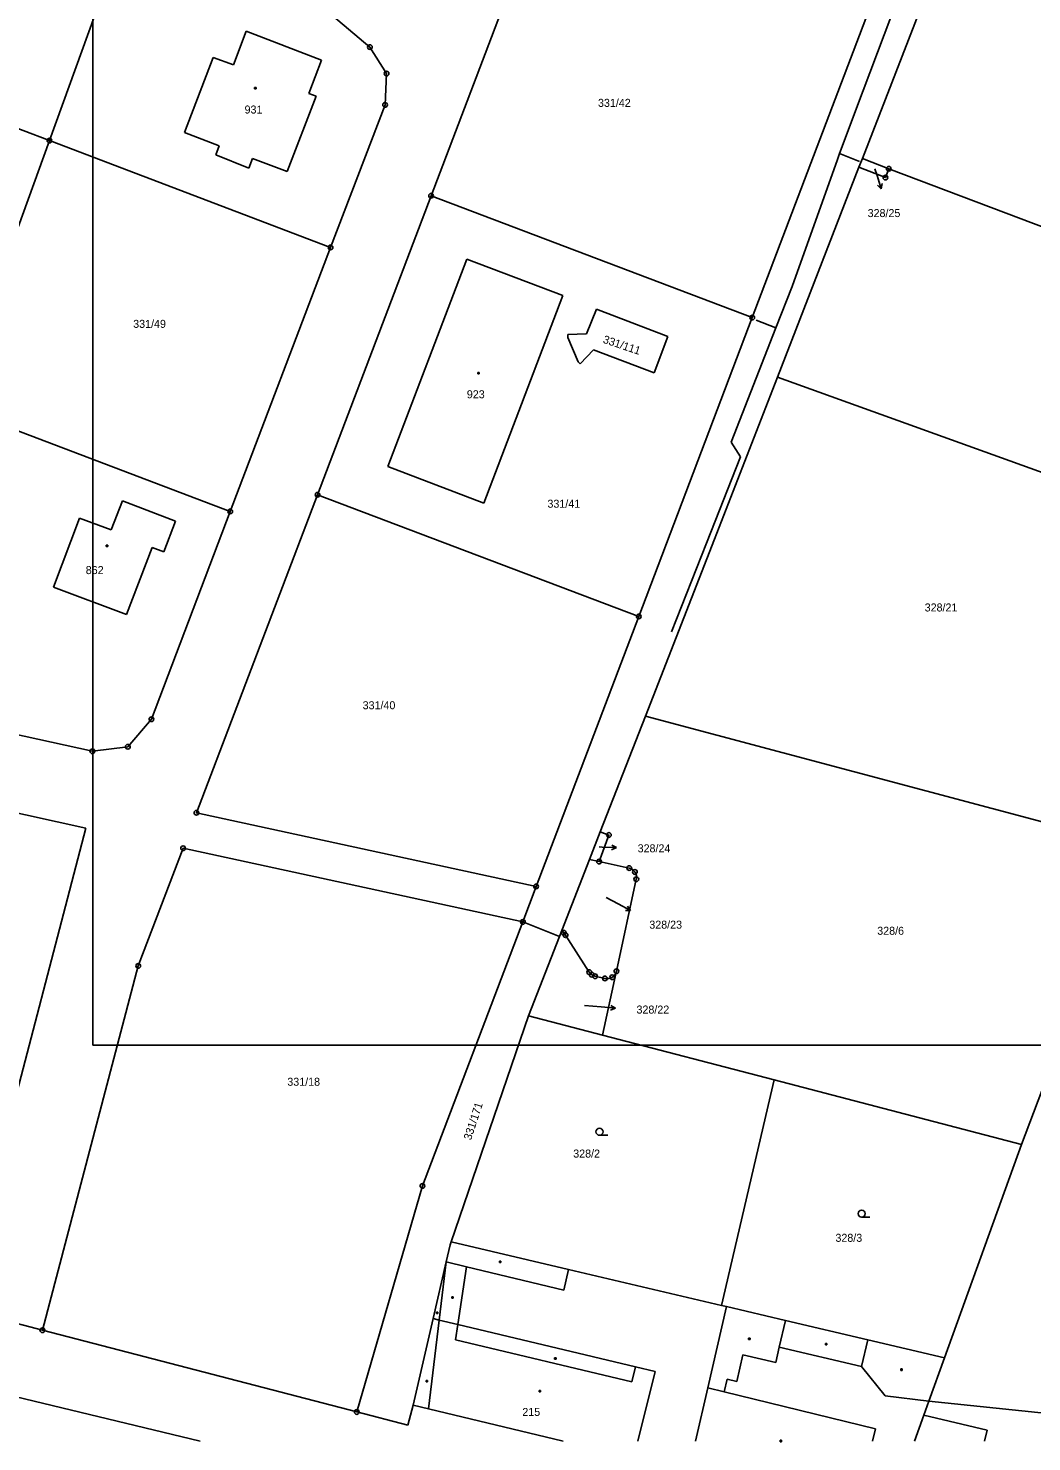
# Model space of a CAD drawing. Extents: x -770973 to -770265, y -1049936 to -1049427.
# Drawn here: x -770865.5 to -770758.9, y -1049934.8 to -1049784.7 of the extents above; entities that cross this region are included whole.
import ezdxf

# ---------------------------------------------------------------- set-up
doc = ezdxf.new("R2010")
doc.units = 0
for name, color, linetype in [('Vrstva 1', 7, 'Continuous'), ('Vrstva 13', 7, 'Continuous'), ('Vrstva 14', 7, 'Continuous'), ('Vrstva 15', 7, 'Continuous'), ('Vrstva 16', 7, 'Continuous'), ('Vrstva 2', 7, 'Continuous'), ('Vrstva 23', 7, 'Continuous'), ('Vrstva 25', 7, 'Continuous'), ('Vrstva 28', 7, 'Continuous'), ('Vrstva 50', 7, 'Continuous'), ('Vrstva 63', 7, 'Continuous')]:
    doc.layers.add(name, color=color, linetype=linetype)

msp = doc.modelspace()

# ---------------------------------------------------------------- linework, layer by layer
at = {"layer": 'Vrstva 1'}
for p, q in [((-770776.92, -1049798.48), (-770755.85, -1049744.21)), ((-770863.27, -1049796.58), (-770852.53, -1049767)), ((-770829.23, -1049786.65), (-770852.53, -1049767)), ((-770822.73, -1049802.44), (-770810.63, -1049770.66)), ((-770788.61, -1049815.38), (-770776.56, -1049783.61)), ((-770893.23, -1049785.23), (-770863.27, -1049796.58)), ((-770842.38, -1049784.96), (-770843.73, -1049788.53)), ((-770834.36, -1049788.05), (-770842.38, -1049784.96)), ((-770827.45, -1049789.46), (-770829.23, -1049786.65)), ((-770845.86, -1049787.74), (-770848.93, -1049795.72)), ((-770843.73, -1049788.53), (-770845.86, -1049787.74)), ((-770835.73, -1049791.59), (-770834.36, -1049788.05)), ((-770827.62, -1049792.79), (-770827.45, -1049789.46)), ((-770838, -1049799.87), (-770834.95, -1049791.88)), ((-770834.95, -1049791.88), (-770835.73, -1049791.59)), ((-770833.4, -1049807.94), (-770827.62, -1049792.79)), ((-770873.5, -1049824.8), (-770863.27, -1049796.58)), ((-770863.27, -1049796.58), (-770833.4, -1049807.94)), ((-770848.93, -1049795.72), (-770845.24, -1049797.13)), ((-770845.24, -1049797.13), (-770845.61, -1049798.11)), ((-770845.61, -1049798.11), (-770842.08, -1049799.5)), ((-770842.08, -1049799.5), (-770841.69, -1049798.48)), ((-770841.69, -1049798.48), (-770838, -1049799.87)), ((-770785.94, -1049821.72), (-770777.28, -1049799.41)), ((-770777.28, -1049799.41), (-770776.92, -1049798.48)), ((-770774.47, -1049800.51), (-770777.28, -1049799.41)), ((-770776.92, -1049798.48), (-770774.11, -1049799.58)), ((-770774.11, -1049799.58), (-770774.47, -1049800.51)), ((-770723.9, -1049818.61), (-770774.11, -1049799.58)), ((-770822.73, -1049802.44), (-770834.79, -1049834.21)), ((-770822.73, -1049802.44), (-770788.61, -1049815.38)), ((-770833.4, -1049807.94), (-770844.07, -1049835.99)), ((-770818.92, -1049809.17), (-770827.31, -1049831.2)), ((-770808.73, -1049813.05), (-770818.92, -1049809.17)), ((-770817.12, -1049835.1), (-770808.73, -1049813.05)), ((-770806.22, -1049817.11), (-770805.17, -1049814.48)), ((-770805.17, -1049814.48), (-770797.57, -1049817.39)), ((-770800.67, -1049847.14), (-770788.61, -1049815.38)), ((-770808.2, -1049817.17), (-770806.22, -1049817.11)), ((-770808.2, -1049817.5), (-770808.2, -1049817.17)), ((-770807.11, -1049820.08), (-770808.2, -1049817.5)), ((-770797.57, -1049817.39), (-770799.05, -1049821.25)), ((-770805.47, -1049818.82), (-770806.88, -1049820.29)), ((-770799.05, -1049821.25), (-770805.47, -1049818.82)), ((-770806.88, -1049820.29), (-770807.11, -1049820.08)), ((-770792.62, -1049838.92), (-770785.94, -1049821.72)), ((-770735.94, -1049839.73), (-770785.94, -1049821.72)), ((-770844.07, -1049835.99), (-770873.5, -1049824.8)), ((-770827.31, -1049831.2), (-770817.12, -1049835.1)), ((-770834.79, -1049834.21), (-770847.66, -1049867.99)), ((-770834.79, -1049834.21), (-770800.67, -1049847.14)), ((-770856.7, -1049837.95), (-770855.51, -1049834.85)), ((-770855.51, -1049834.85), (-770849.86, -1049837)), ((-770862.85, -1049844.02), (-770860.07, -1049836.69)), ((-770860.07, -1049836.69), (-770856.7, -1049837.95)), ((-770844.07, -1049835.99), (-770852.43, -1049858.06)), ((-770849.86, -1049837), (-770851.1, -1049840.27)), ((-770852.35, -1049839.8), (-770855.07, -1049846.94)), ((-770851.1, -1049840.27), (-770852.35, -1049839.8)), ((-770792.62, -1049838.92), (-770799.97, -1049857.75)), ((-770855.07, -1049846.94), (-770862.85, -1049844.02)), ((-770811.57, -1049875.82), (-770800.67, -1049847.14)), ((-770884.71, -1049855.76), (-770858.71, -1049861.47)), ((-770854.94, -1049860.98), (-770852.43, -1049858.06)), ((-770804.76, -1049870.02), (-770799.97, -1049857.75)), ((-770747.99, -1049871.56), (-770799.97, -1049857.75)), ((-770899.58, -1049860.79), (-770859.41, -1049869.62)), ((-770858.71, -1049861.47), (-770854.94, -1049860.98)), ((-770847.66, -1049867.99), (-770811.57, -1049875.82)), ((-770872.73, -1049920.7), (-770859.41, -1049869.62)), ((-770805.9, -1049872.96), (-770804.76, -1049870.02)), ((-770804.76, -1049870.02), (-770803.84, -1049870.36)), ((-770849.07, -1049871.77), (-770853.84, -1049884.27)), ((-770812.98, -1049879.6), (-770849.07, -1049871.77)), ((-770803.84, -1049870.36), (-770804.89, -1049873.18)), ((-770805.9, -1049872.96), (-770808.84, -1049880.5)), ((-770804.89, -1049873.18), (-770805.9, -1049872.96)), ((-770804.89, -1049873.18), (-770801.68, -1049873.87)), ((-770812.98, -1049879.6), (-770811.57, -1049875.82)), ((-770803.05, -1049884.83), (-770800.93, -1049875.06)), ((-770823.65, -1049907.64), (-770812.98, -1049879.6)), ((-770812.98, -1049879.6), (-770809.09, -1049881.13)), ((-770808.84, -1049880.5), (-770809.09, -1049881.13)), ((-770808.84, -1049880.5), (-770808.64, -1049880.74)), ((-770808.64, -1049880.74), (-770808.45, -1049881)), ((-770809.09, -1049881.13), (-770812.38, -1049889.56)), ((-770808.45, -1049881), (-770805.93, -1049884.93)), ((-770853.84, -1049884.27), (-770864.02, -1049922.97)), ((-770805.93, -1049884.93), (-770805.67, -1049885.2)), ((-770805.67, -1049885.2), (-770805.31, -1049885.37)), ((-770804.52, -1049891.61), (-770803.08, -1049884.93)), ((-770803.08, -1049884.93), (-770803.05, -1049884.83)), ((-770805.31, -1049885.37), (-770804.26, -1049885.59)), ((-770820.6, -1049913.58), (-770812.38, -1049889.56)), ((-770804.52, -1049891.61), (-770812.38, -1049889.56)), ((-770786.3, -1049896.37), (-770804.52, -1049891.61)), ((-770791.87, -1049920.34), (-770786.3, -1049896.37)), ((-770760.01, -1049903.23), (-770786.3, -1049896.37)), ((-770760.01, -1049903.23), (-770757.85, -1049897.54)), ((-770760.01, -1049903.23), (-770768.19, -1049925.91)), ((-770830.63, -1049931.66), (-770823.65, -1049907.64)), ((-770820.71, -1049913.9), (-770820.6, -1049913.58)), ((-770808.12, -1049916.52), (-770820.6, -1049913.58)), ((-770820.71, -1049913.9), (-770821.13, -1049915.72)), ((-770821.13, -1049915.72), (-770822.52, -1049921.74)), ((-770791.87, -1049920.34), (-770808.12, -1049916.52)), ((-770872.73, -1049920.7), (-770864.02, -1049922.97)), ((-770793.35, -1049929.1), (-770791.35, -1049920.46)), ((-770791.35, -1049920.46), (-770791.87, -1049920.34)), ((-770785.07, -1049921.94), (-770791.35, -1049920.46)), ((-770822.52, -1049921.74), (-770824.65, -1049930.95)), ((-770776.35, -1049923.99), (-770785.07, -1049921.94)), ((-770864.02, -1049922.97), (-770830.63, -1049931.66)), ((-770768.19, -1049925.91), (-770776.35, -1049923.99)), ((-770847.27, -1049934.76), (-770879.31, -1049927.05)), ((-770768.19, -1049925.91), (-770769.85, -1049930.5)), ((-770794.66, -1049934.76), (-770793.35, -1049929.1)), ((-770830.63, -1049931.66), (-770825.19, -1049933.06)), ((-770825.19, -1049933.06), (-770824.65, -1049930.95)), ((-770824.65, -1049930.95), (-770823.02, -1049931.34)), ((-770823.02, -1049931.34), (-770808.7, -1049934.76)), ((-770769.85, -1049930.5), (-770770.4, -1049932.01)), ((-770740.24, -1049933.6), (-770769.85, -1049930.5)), ((-770770.4, -1049932.01), (-770771.39, -1049934.76)), ((-770763.67, -1049933.58), (-770770.4, -1049932.01)), ((-770763.67, -1049933.58), (-770763.94, -1049934.75))]:
    msp.add_line(p, q, dxfattribs=at)
for centre, radius, start, end in [((-770801.92, -1049874.85), 1.01, 348.2367, 76.2058), ((-770804.01, -1049884.65), 0.974, 255.2851, 343.1534)]:
    msp.add_arc(centre, radius, start, end, dxfattribs=at)
at = {"layer": 'Vrstva 13'}
for p, q in [((-770775.58, -1049799.6), (-770775.36, -1049800.28)), ((-770804.89, -1049871.63), (-770804.54, -1049871.64)), ((-770804.14, -1049876.99), (-770802.85, -1049877.68)), ((-770806.44, -1049888.49), (-770804.65, -1049888.63))]:
    msp.add_line(p, q, dxfattribs=at)
at = {"layer": 'Vrstva 16'}
for p, q in [((-770775.36, -1049800.28), (-770774.91, -1049801.71)), ((-770774.91, -1049801.71), (-770774.82, -1049801.16)), ((-770774.91, -1049801.71), (-770775.3, -1049801.31)), ((-770804.54, -1049871.64), (-770803.04, -1049871.69)), ((-770803.04, -1049871.69), (-770803.55, -1049871.93)), ((-770803.04, -1049871.69), (-770803.53, -1049871.43)), ((-770802.85, -1049877.68), (-770801.53, -1049878.39)), ((-770801.53, -1049878.39), (-770802.09, -1049878.37)), ((-770801.53, -1049878.39), (-770801.85, -1049877.93)), ((-770804.65, -1049888.63), (-770803.15, -1049888.74)), ((-770803.15, -1049888.74), (-770803.67, -1049888.96)), ((-770803.15, -1049888.74), (-770803.63, -1049888.46))]:
    msp.add_line(p, q, dxfattribs=at)
at = {"layer": 'Vrstva 2'}
for p, q in [((-770821.13, -1049915.72), (-770821.88, -1049921.89)), ((-770818.95, -1049916.24), (-770821.13, -1049915.72)), ((-770818.95, -1049916.24), (-770819.88, -1049922.36)), ((-770818.95, -1049916.24), (-770808.64, -1049918.7)), ((-770808.64, -1049918.7), (-770808.12, -1049916.52)), ((-770821.88, -1049921.89), (-770823.02, -1049931.34)), ((-770822.52, -1049921.74), (-770821.88, -1049921.89)), ((-770819.88, -1049922.36), (-770821.88, -1049921.89)), ((-770819.88, -1049922.36), (-770820.12, -1049923.98)), ((-770819.88, -1049922.36), (-770801.02, -1049926.85)), ((-770785.07, -1049921.94), (-770785.74, -1049924.77)), ((-770820.12, -1049923.98), (-770801.4, -1049928.44)), ((-770776.35, -1049923.99), (-770777.02, -1049926.83)), ((-770789.6, -1049925.58), (-770790.27, -1049928.41)), ((-770789.6, -1049925.58), (-770786.12, -1049926.4)), ((-770785.74, -1049924.77), (-770786.12, -1049926.4)), ((-770785.74, -1049924.77), (-770777.02, -1049926.83)), ((-770801.4, -1049928.44), (-770801.02, -1049926.85)), ((-770801.02, -1049926.85), (-770798.92, -1049927.35)), ((-770798.92, -1049927.35), (-770800.78, -1049934.76)), ((-770774.48, -1049929.96), (-770777.02, -1049926.83)), ((-770791.28, -1049928.17), (-770791.61, -1049929.52)), ((-770791.28, -1049928.17), (-770790.27, -1049928.41)), ((-770793.35, -1049929.1), (-770791.61, -1049929.52)), ((-770791.61, -1049929.52), (-770775.51, -1049933.45)), ((-770769.85, -1049930.5), (-770774.48, -1049929.96)), ((-770775.83, -1049934.76), (-770775.51, -1049933.45))]:
    msp.add_line(p, q, dxfattribs=at)
at = {"layer": 'Vrstva 23'}
for p, q in [((-770804.84, -1049902.26), (-770803.96, -1049902.26)), ((-770776.99, -1049910.97), (-770776.11, -1049910.97))]:
    msp.add_line(p, q, dxfattribs=at)
for centre in [(-770804.84, -1049901.89), (-770776.99, -1049910.59)]:
    msp.add_circle(centre, 0.375, dxfattribs=at)
at = {"layer": 'Vrstva 25'}
for p, q in [((-770841.47, -1049790.94), (-770841.32, -1049790.94)), ((-770841.47, -1049791.09), (-770841.47, -1049790.94)), ((-770841.32, -1049791.09), (-770841.47, -1049791.09)), ((-770841.32, -1049790.94), (-770841.32, -1049791.09)), ((-770817.78, -1049821.23), (-770817.63, -1049821.23)), ((-770817.78, -1049821.38), (-770817.78, -1049821.23)), ((-770817.63, -1049821.38), (-770817.78, -1049821.38)), ((-770817.63, -1049821.23), (-770817.63, -1049821.38)), ((-770857.23, -1049839.57), (-770857.08, -1049839.57)), ((-770857.23, -1049839.72), (-770857.23, -1049839.57)), ((-770857.08, -1049839.72), (-770857.23, -1049839.72)), ((-770857.08, -1049839.57), (-770857.08, -1049839.72)), ((-770815.46, -1049915.63), (-770815.31, -1049915.63)), ((-770815.46, -1049915.78), (-770815.46, -1049915.63)), ((-770815.31, -1049915.78), (-770815.46, -1049915.78)), ((-770815.31, -1049915.63), (-770815.31, -1049915.78)), ((-770820.54, -1049919.42), (-770820.39, -1049919.42)), ((-770820.54, -1049919.57), (-770820.54, -1049919.42)), ((-770820.39, -1049919.57), (-770820.54, -1049919.57)), ((-770820.39, -1049919.42), (-770820.39, -1049919.57)), ((-770822.17, -1049921.04), (-770822.02, -1049921.04)), ((-770822.17, -1049921.19), (-770822.17, -1049921.04)), ((-770822.02, -1049921.19), (-770822.17, -1049921.19)), ((-770822.02, -1049921.04), (-770822.02, -1049921.19)), ((-770789, -1049923.8), (-770788.85, -1049923.8)), ((-770789, -1049923.95), (-770789, -1049923.8)), ((-770788.85, -1049923.95), (-770789, -1049923.95)), ((-770788.85, -1049923.8), (-770788.85, -1049923.95)), ((-770780.85, -1049924.37), (-770780.7, -1049924.37)), ((-770780.85, -1049924.52), (-770780.85, -1049924.37)), ((-770780.7, -1049924.52), (-770780.85, -1049924.52)), ((-770780.7, -1049924.37), (-770780.7, -1049924.52)), ((-770809.61, -1049925.91), (-770809.46, -1049925.91)), ((-770809.61, -1049926.06), (-770809.61, -1049925.91)), ((-770809.46, -1049926.06), (-770809.61, -1049926.06)), ((-770809.46, -1049925.91), (-770809.46, -1049926.06)), ((-770772.85, -1049927.09), (-770772.7, -1049927.09)), ((-770772.85, -1049927.24), (-770772.85, -1049927.09)), ((-770772.7, -1049927.24), (-770772.85, -1049927.24)), ((-770772.7, -1049927.09), (-770772.7, -1049927.24)), ((-770823.25, -1049928.3), (-770823.1, -1049928.3)), ((-770823.25, -1049928.45), (-770823.25, -1049928.3)), ((-770823.1, -1049928.45), (-770823.25, -1049928.45)), ((-770823.1, -1049928.3), (-770823.1, -1049928.45)), ((-770811.24, -1049929.38), (-770811.09, -1049929.38)), ((-770811.24, -1049929.53), (-770811.24, -1049929.38)), ((-770811.09, -1049929.53), (-770811.24, -1049929.53)), ((-770811.09, -1049929.38), (-770811.09, -1049929.53)), ((-770785.66, -1049934.67), (-770785.51, -1049934.67)), ((-770785.66, -1049934.82), (-770785.66, -1049934.67)), ((-770785.51, -1049934.82), (-770785.66, -1049934.82)), ((-770785.51, -1049934.67), (-770785.51, -1049934.82))]:
    msp.add_line(p, q, dxfattribs=at)
at = {"layer": 'Vrstva 28'}
for centre, radius in [((-770829.23, -1049786.65), 0.25), ((-770829.23, -1049786.65), 0.005), ((-770827.45, -1049789.46), 0.25), ((-770827.45, -1049789.46), 0.005), ((-770827.62, -1049792.79), 0.25), ((-770827.62, -1049792.79), 0.005), ((-770863.27, -1049796.58), 0.25), ((-770863.27, -1049796.58), 0.005), ((-770774.11, -1049799.58), 0.25), ((-770774.11, -1049799.58), 0.005), ((-770774.47, -1049800.51), 0.25), ((-770774.47, -1049800.51), 0.005), ((-770822.73, -1049802.44), 0.25), ((-770822.73, -1049802.44), 0.005), ((-770833.4, -1049807.94), 0.25), ((-770833.4, -1049807.94), 0.005), ((-770788.61, -1049815.38), 0.25), ((-770788.61, -1049815.38), 0.005), ((-770834.79, -1049834.21), 0.25), ((-770834.79, -1049834.21), 0.005), ((-770844.07, -1049835.99), 0.25), ((-770844.07, -1049835.99), 0.005), ((-770800.67, -1049847.14), 0.25), ((-770800.67, -1049847.14), 0.005), ((-770852.43, -1049858.06), 0.25), ((-770852.43, -1049858.06), 0.005), ((-770858.71, -1049861.47), 0.25), ((-770854.94, -1049860.98), 0.25), ((-770854.94, -1049860.98), 0.005), ((-770858.71, -1049861.47), 0.005), ((-770847.66, -1049867.99), 0.25), ((-770847.66, -1049867.99), 0.005), ((-770803.84, -1049870.36), 0.25), ((-770849.07, -1049871.77), 0.25), ((-770849.07, -1049871.77), 0.005), ((-770803.84, -1049870.36), 0.005), ((-770804.89, -1049873.18), 0.25), ((-770804.89, -1049873.18), 0.005), ((-770801.68, -1049873.87), 0.25), ((-770801.68, -1049873.87), 0.005), ((-770801.08, -1049874.29), 0.25), ((-770801.08, -1049874.29), 0.005), ((-770811.57, -1049875.82), 0.25), ((-770811.57, -1049875.82), 0.005), ((-770800.93, -1049875.06), 0.25), ((-770800.93, -1049875.06), 0.005), ((-770812.98, -1049879.6), 0.25), ((-770812.98, -1049879.6), 0.005), ((-770808.64, -1049880.74), 0.25), ((-770808.45, -1049881), 0.25), ((-770808.64, -1049880.74), 0.005), ((-770808.45, -1049881), 0.005), ((-770853.84, -1049884.27), 0.25), ((-770853.84, -1049884.27), 0.005), ((-770805.93, -1049884.93), 0.25), ((-770805.93, -1049884.93), 0.005), ((-770805.67, -1049885.2), 0.25), ((-770805.67, -1049885.2), 0.005), ((-770805.31, -1049885.37), 0.25), ((-770803.49, -1049885.47), 0.25), ((-770803.05, -1049884.83), 0.25), ((-770803.05, -1049884.83), 0.005), ((-770805.31, -1049885.37), 0.005), ((-770804.26, -1049885.59), 0.25), ((-770804.26, -1049885.59), 0.005), ((-770803.49, -1049885.47), 0.005), ((-770823.65, -1049907.64), 0.25), ((-770823.65, -1049907.64), 0.005), ((-770864.02, -1049922.97), 0.25), ((-770864.02, -1049922.97), 0.005), ((-770830.63, -1049931.66), 0.25), ((-770830.63, -1049931.66), 0.005)]:
    msp.add_circle(centre, radius, dxfattribs=at)
at = {"layer": 'Vrstva 50'}
for p, q in [((-770772.14, -1049778.81), (-770776.83, -1049791.27)), ((-770776.83, -1049791.27), (-770779.34, -1049797.94)), ((-770779.34, -1049797.94), (-770779.56, -1049798.6)), ((-770779.34, -1049797.94), (-770777.23, -1049798.79)), ((-770779.56, -1049798.6), (-770784.39, -1049812.08)), ((-770784.39, -1049812.08), (-770786.1, -1049816.48)), ((-770786.1, -1049816.48), (-770788.21, -1049815.66)), ((-770786.1, -1049816.48), (-770790.84, -1049828.61)), ((-770790.84, -1049828.61), (-770789.88, -1049830.18)), ((-770789.88, -1049830.18), (-770793.49, -1049839.34)), ((-770793.49, -1049839.34), (-770797.21, -1049848.78))]:
    msp.add_line(p, q, dxfattribs=at)
at = {"layer": 'Vrstva 63'}
msp.add_lwpolyline([(-770858.67, -1049892.7), (-770264.67, -1049892.7), (-770264.67, -1049472.7), (-770858.67, -1049472.7), (-770858.67, -1049892.7)], dxfattribs=at)

# ---------------------------------------------------------------- texts
at = {"layer": 'Vrstva 14'}
for s, height, p in [('331/42', 0.85, (-770805, -1049793)), ('328/25', 0.05, (-770775.58, -1049799.6)), ('331/49', 0.85, (-770854.37, -1049816.48)), ('331/41', 0.85, (-770810.37, -1049835.59)), ('328/21', 0.85, (-770770.3, -1049846.61)), ('331/40', 0.85, (-770830, -1049857)), ('328/24', 0.05, (-770804.89, -1049871.63)), ('328/23', 0.05, (-770804.14, -1049876.99)), ('328/6', 0.85, (-770775.34, -1049880.96)), ('328/22', 0.05, (-770806.44, -1049888.49)), ('331/18', 0.85, (-770838, -1049897)), ('328/2', 0.85, (-770807.63, -1049904.63)), ('328/3', 0.85, (-770779.78, -1049913.58))]:
    msp.add_text(s, height=height, dxfattribs=at).set_placement(p)
for s, rotation, p in [('331/111', 341.4913, (-770804.54, -1049818.05)), ('331/171', 72, (-770818.49, -1049902.84))]:
    msp.add_text(s, height=0.85, rotation=rotation, dxfattribs=at).set_placement(p)
at = {"layer": 'Vrstva 15'}
for s, p in [('931', (-770842.54, -1049793.71)), ('923', (-770818.93, -1049823.96)), ('862', (-770859.41, -1049842.64)), ('215', (-770813.04, -1049932.08))]:
    msp.add_text(s, height=0.85, dxfattribs=at).set_placement(p)
at = {"layer": 'Vrstva 16'}
for s, p in [('328/25', (-770776.36, -1049804.71)), ('328/24', (-770800.79, -1049872.2)), ('328/23', (-770799.55, -1049880.31)), ('328/22', (-770800.91, -1049889.33))]:
    msp.add_text(s, height=0.85, dxfattribs=at).set_placement(p)

doc.saveas('drawing.dxf')
